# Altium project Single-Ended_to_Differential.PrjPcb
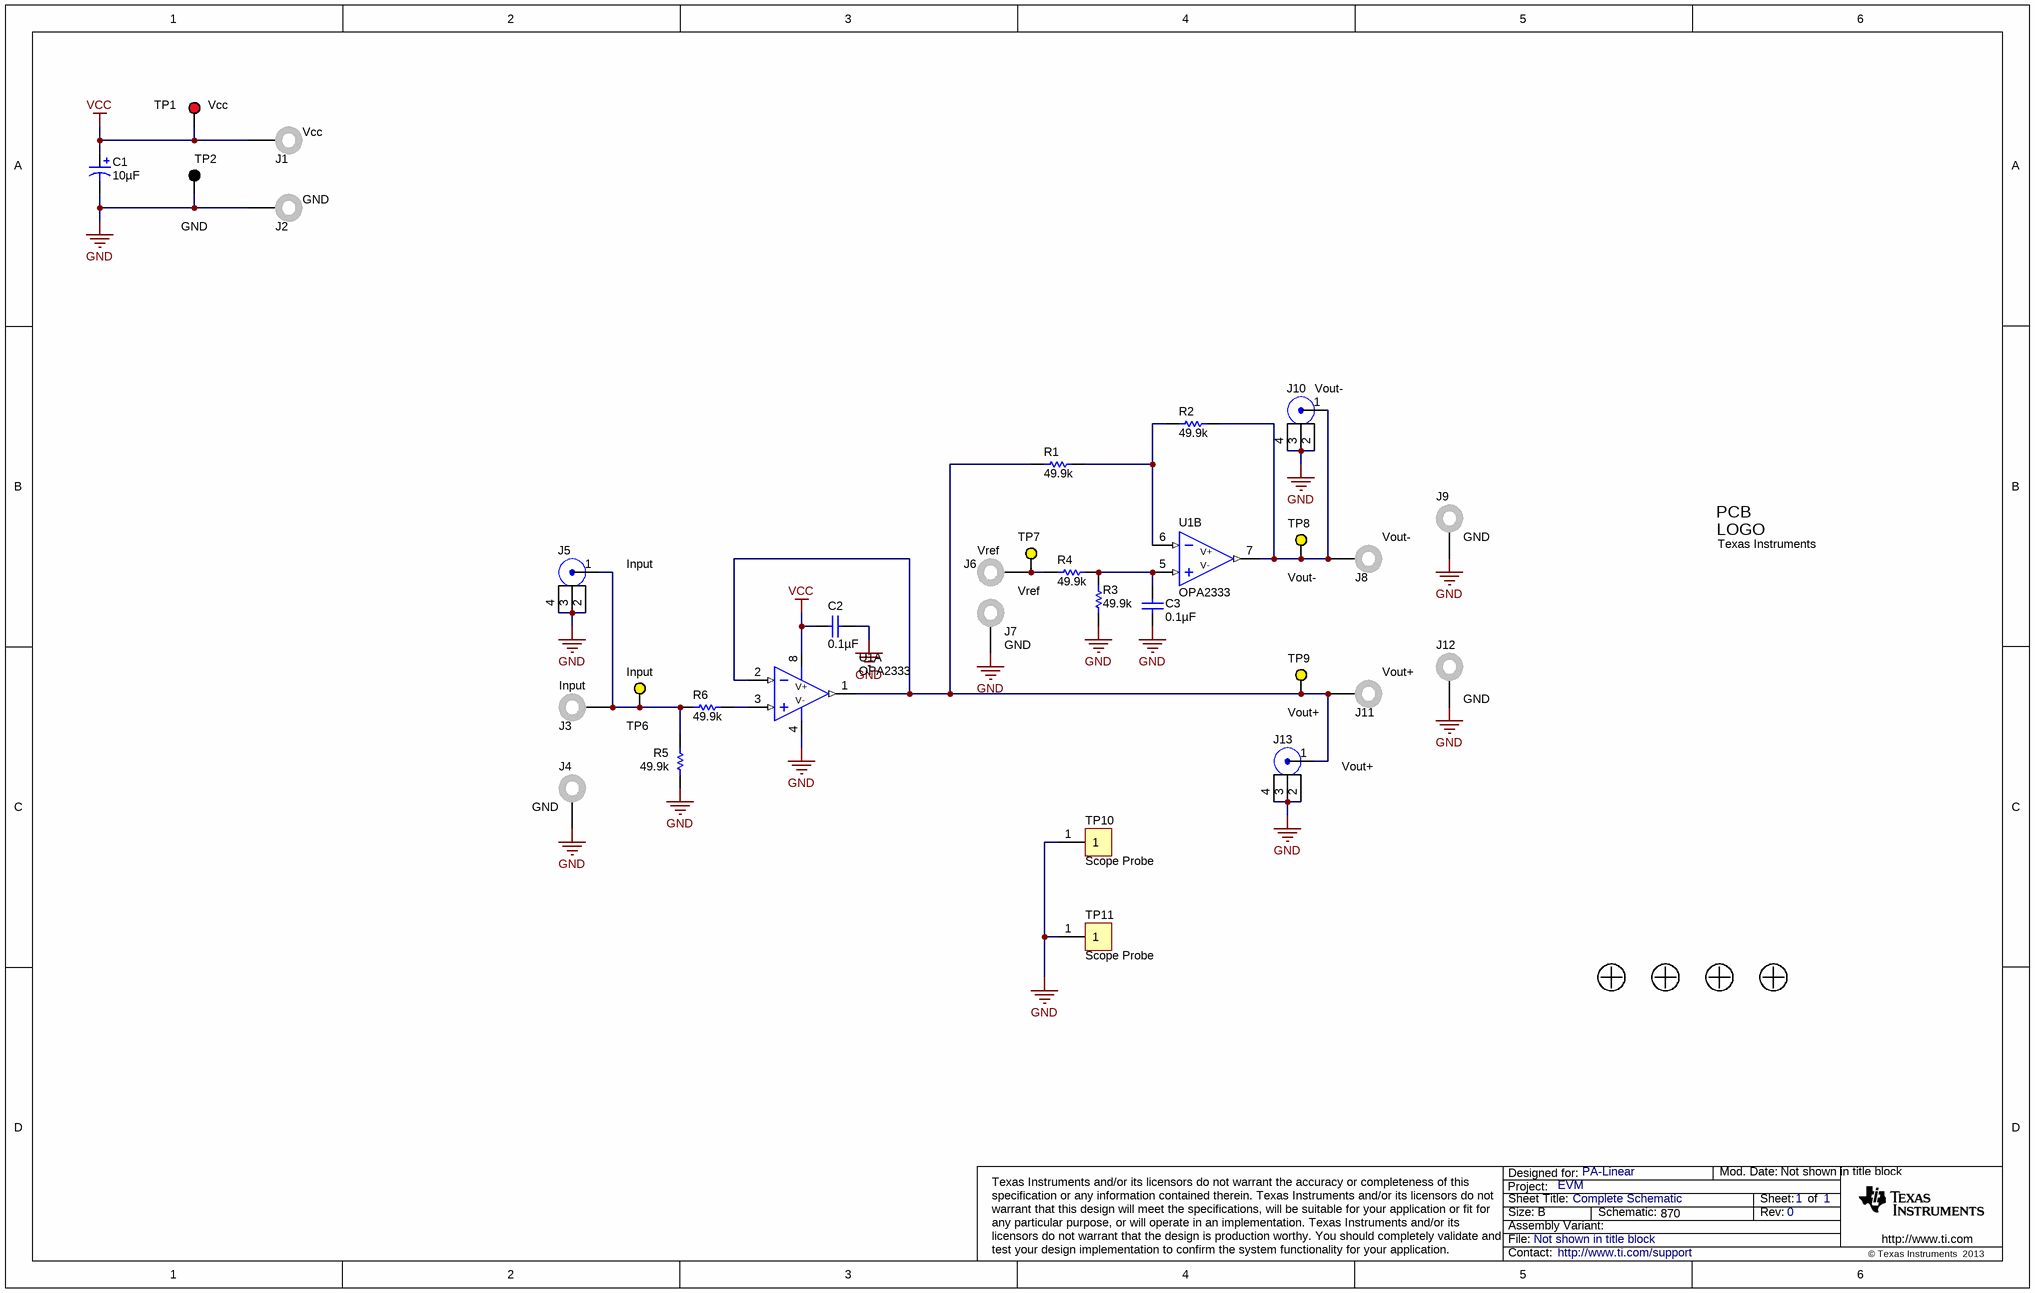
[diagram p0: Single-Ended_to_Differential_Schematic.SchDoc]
CopyrightYear: 2013; PRJ_Customer: PA-Linear; PRJ_Title: EVM; SCH_Rev: 0; TechSupport: http://www.ti.com/support
1 sheet, 36 parts. Net scope: global (net labels, ports and power ports of the same name join across sheets).
Board file: Single-Ended In to Differential Out.PcbDoc

## Sheet Single-Ended_to_Differential_Schematic.SchDoc: Complete Schematic
size B; Date: Not shown in title block; ApprovedBy: Not shown in title block; CheckedBy: Not shown in title block; Author: Not shown in title block; CompanyName: Not shown in title block; DrawnBy: Not shown in title block; Engineer: Not shown in title block; Organization: Not shown in title block; Address1: Not shown in title block; Address2: Not shown in title block; Address3: Not shown in title block; Address4: Not shown in title block; DocumentNumber: 1; Revision: Use project parameter SCH_Rev; SheetNumber: 1; SheetTotal: 1; PageSetup: Record=PageOptions|CenterHorizontal=True|CenterVertical=True|PrintScale=0.72|XCorrection=1.00|YCorrection=1.00|PrintKind=0|BorderSize=5000000|LeftOffset=0|BottomOffset=0|Orientation=2|PaperLength=1000|PaperWidth=1000|Scale=100|PaperSource=15|PrintQuality=600|MediaType=1|DitherType=10|PaperKind=Letter|PrintScaleMode=1

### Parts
C1  ValueDisplayed: 10µF  [3528-21]  (hidden comment: TPSB106M020R1000)
C2  ValueDisplayed: 0.1µF  [0603]  (hidden comment: GRM188R71H104KA93D)
C3  ValueDisplayed: 0.1µF  [0603]  (hidden comment: GRM188R71H104KA93D)
J1  Vcc  [JACK NON-INSULATED .218"]
J2  GND  [JACK NON-INSULATED .218"]
J3  Input  [JACK NON-INSULATED .218"]
J4  GND  [JACK NON-INSULATED .218"]
J5  Input  [Right Angle BNC]
J6  Vref  [JACK NON-INSULATED .218"]
J7  GND  [JACK NON-INSULATED .218"]
J8  Vout-  [JACK NON-INSULATED .218"]
J9  GND  [JACK NON-INSULATED .218"]
J10  Vout-  [Right Angle BNC]
J11  Vout+  [JACK NON-INSULATED .218"]
J12  GND  [JACK NON-INSULATED .218"]
J13  Vout+  [Right Angle BNC]
Logo1  Texas Instruments  [TI_Symbol_Overlay_Small]  (no BOM)
R1  49.9k  [0603]
R2  value 49.9k  [0603]  (hidden comment: CRCW06031K00FKEA)
R3  value 49.9k  [0603]  (hidden comment: CRCW06031K00FKEA)
R4  value 49.9k  [0603]  (hidden comment: 1k00)
R5  49.9k  [0603]
R6  49.9k  [0603]
TP1  Vcc  [Keystone5005]
TP2  GND  [Keystone5006]
TP6  Input  [Keystone5009]
TP7  Vref  [Keystone5009]
TP8  Vout-  [Keystone5009]
TP9  Vout+  [Keystone5009]
TP10  Scope Probe  [tg pad]
TP11  Scope Probe  [tg pad]
U1  OPA2333  [M08A_L]  (parts A,B of 2)
U90  NY PMS 440 0025 PH  [NY PMS 440 0025 PH]  (value not drawn)
U91  NY PMS 440 0025 PH  [NY PMS 440 0025 PH]  (value not drawn)
U92  NY PMS 440 0025 PH  [NY PMS 440 0025 PH]  (value not drawn)
U93  NY PMS 440 0025 PH  [NY PMS 440 0025 PH]  (value not drawn)

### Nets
GND: C1.2(-) C2.1 C3.2 J2.1 J4.1 J5.2 J5.3 J5.4 J7.1 J9.1 J10.2 J10.3 J10.4 J12.1 J13.2 J13.3 J13.4 R3.1 R5.1 TP2.1 TP10.1 TP11.1 U1.4(V-)
VCC: C1.1(+) C2.2 J1.1 TP1.1 U1.8(V+)
NetC3_1: C3.1 R3.2 R4.2 U1.5(IN+)
NetJ3_1: J3.1 J5.1 R5.2 R6.1 TP6.1
NetJ6_1: J6.1 R4.1 TP7.1
NetJ8_1: J8.1 J10.1 R2.2 TP8.1 U1.7(OUT)
NetJ11_1: J11.1 J13.1 R1.1 TP9.1 U1.1(OUT) U1.2(IN-)
NetR1_2: R1.2 R2.1 U1.6(IN-)
NetR6_2: R6.2 U1.3(IN+)

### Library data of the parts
C1 = TPSB106M020R1000: CAP, TANT, 10uF, 20V, +/-20%, 1 ohm, 3528-21 SMD; Manufacturer: AVX; Polarized: Y; CompType: Capacitor; U/M: EA; Cap_F: 0.00001; Tolerance_%: 20; Value1: 1 ohm; ESR_Ohm: 1; IRMS_A: 0.262; TaMin_C: -55; TaMax_C: 125; Cap_Case: B
C2 C3 = GRM188R71H104KA93D: CAP, CERM, 0.1uF, 50V, +/-10%, X7R, 0603; Manufacturer: MuRata; Polarized: N; CompType: Capacitor; U/M: EA; Cap_F: 0.0000001; Tolerance_%: 10; Value1: Unknown; VDC_V: 50; TaMin_C: -55; TaMax_C: 125
J1-J4 J6-J9 J11 J12 = Banana Jack, Solder: JACK NON-INSULATED .218"; Manufacturer: Keystone; PartNumber: 575-4; SymbolVersion: use current date i.e. 2008-05-20; SymbolCreator: Use LDAP id; CompType: Used in some BOM reports.  Useful for finding later.; U/M: EA, IN, or GM
J5 J10 J13 = BNC Right Angle: BNC; Manufacturer: TE Connectivity; PartNumber: Used in BOM report; SymbolVersion: use current date i.e. 2008-05-20; SymbolCreator: Use LDAP id; CompType: Used in some BOM reports.  Useful for finding later.; U/M: EA, IN, or GM
Logo1 = TI_Logo: Texas Instrument Corporate Signature; SymbolCreator: codlsc
R1-R3 R5 R6 = CRCW06031K00FKEA: RES, 1.00k ohm, 1%, 0.1W, 0603; Manufacturer: Vishay-Dale; CompType: Resistor; Res_ohm: 1000; Value_Code: 1k00; Tolerance_%: 1; Power_W: 0.1; VDC_V: 75; TempCo: 100 ppm/C; EIA_Code: E96; U/M: EA
R4 = CRCW06031K00FKEA: RES, 1.00k ohm, 1%, 0.1W, 0603; Manufacturer: Vishay-Dale; CompType: Resistor; Res_ohm: 1000; Tolerance_%: 1; Power_W: 0.1; VDC_V: 75; TempCo: 100 ppm/C; EIA_Code: E96; U/M: EA
TP1 = 5005: Test Point, TH, Compact, Red; Manufacturer: Keystone; Alternate Manufacturer: Any; Alternate PartNumber: Equivalent; CompType: Test Point Loop; U/M: EA
TP2 = 5006: Test Point, TH, Compact, Black; Manufacturer: Keystone; Alternate Manufacturer: Any; Alternate PartNumber: Equivalent; CompType: Test Point Loop; U/M: EA
TP6-TP9 = 5009: Test Point, TH, Compact, Yellow; Manufacturer: Keystone; Alternate Manufacturer: Any; Alternate PartNumber: Equivalent; CompType: Test Point Loop; U/M: EA
TP10 TP11 = tg pad: Ground Pad; SymbolVersion: use current date i.e. 2008-05-20; SymbolCreator: Use a-id; CompType: Used in some BOM reports.  Useful for finding later.; U/M: EA, IN, or GM
U1 = OPA2333: Manufacturer: Texas Instruments; Characteristics: 1.8V, High CMR, RRIO Op Amp; CompType: OpAmp IC; Value: LF353M; TaMin_C: 0.0; TaMax_C: 70.0; PowerWise: N
U90-U93 = NY PMS 440 0025 PH: Machine Screw, Round, #4-40 x 1/4, Nylon, Philips panhead; Manufacturer: B&F Fastener Supply; SymbolCreator: codlsc; CompType: Hardware; U/M: EA

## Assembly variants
-100A: all parts fitted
